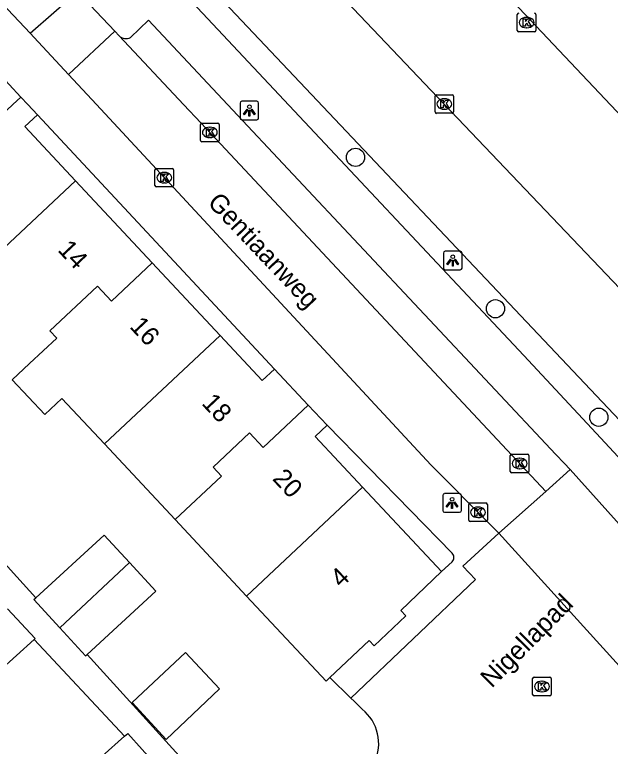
# Model space of a CAD drawing. Extents: x 162347 to 162868, y 381221 to 381813.
# Drawn here: x 162687 to 162719, y 381465.54 to 381504.82 of the extents above; entities that cross this region are included whole.
import ezdxf

# ---------------------------------------------------------------- set-up
doc = ezdxf.new("R2010")
doc.units = 0
for name, color, linetype in [('IMGEO_Boom', 7, 'Continuous'), ('IMGEO_Kolk', 7, 'Continuous'), ('IMGEO_Lichtpunt', 7, 'Continuous'), ('IMGEO_Muur', 7, 'Continuous'), ('IMGEO_Openbare_ruimte_label', 7, 'Continuous'), ('IMGEO_Pand', 7, 'Continuous'), ('IMGEO_Pand_nummerreeks', 7, 'Continuous'), ('IMGEO_Parkeervlak_open', 7, 'Continuous'), ('IMGEO_Rijbaan_lokaal_gesloten', 7, 'Continuous'), ('IMGEO_Rijbaan_lokaal_open', 7, 'Continuous'), ('IMGEO_Voetpad_open', 7, 'Continuous')]:
    doc.layers.add(name, color=color, linetype=linetype)

msp = doc.modelspace()

# ---------------------------------------------------------------- linework, layer by layer
at = {"layer": 'IMGEO_Boom'}
for centre in [(162705.311, 381497.163), (162712.828, 381489.032), (162718.381, 381483.208)]:
    msp.add_circle(centre, 0.489, dxfattribs=at)
at = {"layer": 'IMGEO_Kolk'}
for p, q in [((162714.002, 381503.972), (162714.002, 381504.824)), ((162714.49, 381504.678), (162714.515, 381504.678)), ((162715.003, 381504.824), (162715.003, 381503.972)), ((162714.513, 381504.118), (162714.488, 381504.118)), ((162714.929, 381503.898), (162714.077, 381503.898)), ((162709.581, 381499.599), (162709.581, 381500.451)), ((162709.656, 381500.525), (162710.508, 381500.525)), ((162710.069, 381500.305), (162710.094, 381500.305)), ((162710.582, 381500.451), (162710.582, 381499.599)), ((162710.508, 381499.525), (162709.656, 381499.525)), ((162710.092, 381499.745), (162710.067, 381499.745)), ((162697.06, 381499.001), (162697.912, 381499.001)), ((162696.985, 381498.075), (162696.985, 381498.927)), ((162697.473, 381498.781), (162697.498, 381498.781)), ((162697.986, 381498.927), (162697.986, 381498.075)), ((162697.496, 381498.221), (162697.471, 381498.221)), ((162697.912, 381498.001), (162697.06, 381498.001)), ((162694.537, 381495.645), (162694.537, 381496.497)), ((162694.612, 381496.571), (162695.464, 381496.571)), ((162695.025, 381496.351), (162695.05, 381496.351)), ((162695.538, 381496.497), (162695.538, 381495.645)), ((162695.464, 381495.571), (162694.612, 381495.571)), ((162695.048, 381495.791), (162695.023, 381495.791)), ((162713.626, 381480.298), (162713.626, 381481.15)), ((162713.701, 381481.224), (162714.553, 381481.224)), ((162714.114, 381481.004), (162714.139, 381481.004)), ((162714.627, 381481.15), (162714.627, 381480.298)), ((162714.553, 381480.224), (162713.701, 381480.224)), ((162714.137, 381480.444), (162714.112, 381480.444)), ((162711.466, 381478.603), (162712.318, 381478.603)), ((162711.391, 381477.677), (162711.391, 381478.529)), ((162711.879, 381478.383), (162711.904, 381478.383)), ((162712.392, 381478.529), (162712.392, 381477.677)), ((162711.902, 381477.823), (162711.877, 381477.823)), ((162712.318, 381477.603), (162711.466, 381477.603)), ((162714.825, 381468.323), (162714.825, 381469.175)), ((162714.9, 381469.249), (162715.752, 381469.249)), ((162715.826, 381469.175), (162715.826, 381468.323)), ((162715.313, 381469.029), (162715.338, 381469.029)), ((162715.336, 381468.469), (162715.311, 381468.469)), ((162715.752, 381468.249), (162714.9, 381468.249))]:
    msp.add_line(p, q, dxfattribs=at)
for points in [[(162714.002, 381503.972), (162714.002, 381504.824)], [(162714.323, 381504.598), (162714.446, 381504.598), (162714.446, 381504.447), (162714.576, 381504.598), (162714.74, 381504.598), (162714.594, 381504.447), (162714.747, 381504.198), (162714.595, 381504.198), (162714.51, 381504.362), (162714.446, 381504.295), (162714.446, 381504.198), (162714.323, 381504.198), (162714.323, 381504.598)], [(162715.003, 381504.824), (162715.003, 381503.972)], [(162714.929, 381503.898), (162714.077, 381503.898)], [(162709.581, 381499.599), (162709.581, 381500.451)], [(162709.656, 381500.525), (162710.508, 381500.525)], [(162709.902, 381500.225), (162710.025, 381500.225), (162710.025, 381500.074), (162710.155, 381500.225), (162710.319, 381500.225), (162710.173, 381500.074), (162710.326, 381499.825), (162710.174, 381499.825), (162710.089, 381499.989), (162710.025, 381499.922), (162710.025, 381499.825), (162709.902, 381499.825), (162709.902, 381500.225)], [(162710.582, 381500.451), (162710.582, 381499.599)], [(162710.508, 381499.525), (162709.656, 381499.525)], [(162697.06, 381499.001), (162697.912, 381499.001)], [(162696.985, 381498.075), (162696.985, 381498.927)], [(162697.306, 381498.701), (162697.429, 381498.701), (162697.429, 381498.55), (162697.559, 381498.701), (162697.723, 381498.701), (162697.577, 381498.55), (162697.73, 381498.301), (162697.578, 381498.301), (162697.493, 381498.465), (162697.429, 381498.398), (162697.429, 381498.301), (162697.306, 381498.301), (162697.306, 381498.701)], [(162697.986, 381498.927), (162697.986, 381498.075)], [(162697.912, 381498.001), (162697.06, 381498.001)], [(162694.537, 381495.645), (162694.537, 381496.497)], [(162694.612, 381496.571), (162695.464, 381496.571)], [(162694.858, 381496.271), (162694.981, 381496.271), (162694.981, 381496.12), (162695.111, 381496.271), (162695.275, 381496.271), (162695.129, 381496.12), (162695.282, 381495.871), (162695.13, 381495.871), (162695.045, 381496.035), (162694.981, 381495.968), (162694.981, 381495.871), (162694.858, 381495.871), (162694.858, 381496.271)], [(162695.538, 381496.497), (162695.538, 381495.645)], [(162695.464, 381495.571), (162694.612, 381495.571)], [(162713.626, 381480.298), (162713.626, 381481.15)], [(162713.701, 381481.224), (162714.553, 381481.224)], [(162713.947, 381480.924), (162714.07, 381480.924), (162714.07, 381480.773), (162714.2, 381480.924), (162714.364, 381480.924), (162714.218, 381480.773), (162714.371, 381480.524), (162714.219, 381480.524), (162714.134, 381480.688), (162714.07, 381480.621), (162714.07, 381480.524), (162713.947, 381480.524), (162713.947, 381480.924)], [(162714.627, 381481.15), (162714.627, 381480.298)], [(162714.553, 381480.224), (162713.701, 381480.224)], [(162711.466, 381478.603), (162712.318, 381478.603)], [(162711.391, 381477.677), (162711.391, 381478.529)], [(162711.712, 381478.303), (162711.835, 381478.303), (162711.835, 381478.152), (162711.965, 381478.303), (162712.129, 381478.303), (162711.983, 381478.152), (162712.136, 381477.903), (162711.984, 381477.903), (162711.899, 381478.067), (162711.835, 381478), (162711.835, 381477.903), (162711.712, 381477.903), (162711.712, 381478.303)], [(162712.392, 381478.529), (162712.392, 381477.677)], [(162712.318, 381477.603), (162711.466, 381477.603)], [(162714.825, 381468.323), (162714.825, 381469.175)], [(162714.9, 381469.249), (162715.752, 381469.249)], [(162715.826, 381469.175), (162715.826, 381468.323)], [(162715.146, 381468.949), (162715.269, 381468.949), (162715.269, 381468.798), (162715.399, 381468.949), (162715.563, 381468.949), (162715.417, 381468.798), (162715.57, 381468.549), (162715.418, 381468.549), (162715.333, 381468.713), (162715.269, 381468.646), (162715.269, 381468.549), (162715.146, 381468.549), (162715.146, 381468.949)], [(162715.752, 381468.249), (162714.9, 381468.249)]]:
    msp.add_lwpolyline(points, dxfattribs=at)
for centre, start, end in [((162714.079, 381504.822), 91.552, 178.448), ((162714.079, 381504.822), 91.552, 178.448), ((162714.927, 381504.822), 1.552, 88.448), ((162714.927, 381504.822), 1.552, 88.448), ((162714.079, 381503.974), 181.552, 268.448), ((162714.079, 381503.974), 181.552, 268.448), ((162714.927, 381503.974), 271.552, 358.448), ((162714.927, 381503.974), 271.552, 358.448), ((162709.658, 381500.449), 91.552, 178.448), ((162709.658, 381500.449), 91.552, 178.448), ((162710.506, 381500.449), 1.552, 88.448), ((162710.506, 381500.449), 1.552, 88.448), ((162709.658, 381499.601), 181.552, 268.448), ((162709.658, 381499.601), 181.552, 268.448), ((162710.506, 381499.601), 271.552, 358.448), ((162710.506, 381499.601), 271.552, 358.448), ((162697.062, 381498.925), 91.552, 178.448), ((162697.062, 381498.925), 91.552, 178.448), ((162697.91, 381498.925), 1.552, 88.448), ((162697.91, 381498.925), 1.552, 88.448), ((162697.062, 381498.077), 181.552, 268.448), ((162697.062, 381498.077), 181.552, 268.448), ((162697.91, 381498.077), 271.552, 358.448), ((162697.91, 381498.077), 271.552, 358.448), ((162694.614, 381496.495), 91.552, 178.448), ((162694.614, 381496.495), 91.552, 178.448), ((162695.462, 381496.495), 1.552, 88.448), ((162695.462, 381496.495), 1.552, 88.448), ((162694.614, 381495.647), 181.552, 268.448), ((162694.614, 381495.647), 181.552, 268.448), ((162695.462, 381495.647), 271.552, 358.448), ((162695.462, 381495.647), 271.552, 358.448), ((162713.703, 381481.148), 91.552, 178.448), ((162713.703, 381481.148), 91.552, 178.448), ((162714.551, 381481.148), 1.552, 88.448), ((162714.551, 381481.148), 1.552, 88.448), ((162713.703, 381480.3), 181.552, 268.448), ((162713.703, 381480.3), 181.552, 268.448), ((162714.551, 381480.3), 271.552, 358.448), ((162714.551, 381480.3), 271.552, 358.448), ((162711.468, 381478.527), 91.552, 178.448), ((162711.468, 381478.527), 91.552, 178.448), ((162712.316, 381478.527), 1.552, 88.448), ((162712.316, 381478.527), 1.552, 88.448), ((162711.468, 381477.679), 181.552, 268.448), ((162711.468, 381477.679), 181.552, 268.448), ((162712.316, 381477.679), 271.552, 358.448), ((162712.316, 381477.679), 271.552, 358.448), ((162714.902, 381469.173), 91.552, 178.448), ((162714.902, 381469.173), 91.552, 178.448), ((162715.75, 381469.173), 1.552, 88.448), ((162715.75, 381469.173), 1.552, 88.448), ((162714.902, 381468.325), 181.552, 268.448), ((162714.902, 381468.325), 181.552, 268.448), ((162715.75, 381468.325), 271.552, 358.448), ((162715.75, 381468.325), 271.552, 358.448)]:
    msp.add_arc(centre, 0.0765, start, end, dxfattribs=at)
for centre, major_axis, ratio, start_param, end_param in [((162714.489, 381504.398), (-0.387, 0.002), 0.722429, 4.712389, 7.853982), ((162714.514, 381504.398), (-0.39, 0.002), 0.717154, 1.570796, 4.712389), ((162710.068, 381500.025), (-0.387, 0.002), 0.722429, 4.712389, 7.853982), ((162710.093, 381500.025), (-0.39, 0.002), 0.717154, 1.570796, 4.712389), ((162697.472, 381498.501), (-0.387, 0.002), 0.722429, 4.712389, 7.853982), ((162697.497, 381498.501), (-0.39, 0.002), 0.717154, 1.570796, 4.712389), ((162695.024, 381496.071), (-0.387, 0.002), 0.722429, 4.712389, 7.853982), ((162695.049, 381496.071), (-0.39, 0.002), 0.717154, 1.570796, 4.712389), ((162714.113, 381480.724), (-0.387, 0.002), 0.722429, 4.712389, 7.853982), ((162714.138, 381480.724), (-0.39, 0.002), 0.717154, 1.570796, 4.712389), ((162711.878, 381478.103), (-0.387, 0.002), 0.722429, 4.712389, 7.853982), ((162711.903, 381478.103), (-0.39, 0.002), 0.717154, 1.570796, 4.712389), ((162715.312, 381468.749), (-0.387, 0.002), 0.722429, 4.712389, 7.853982), ((162715.337, 381468.749), (-0.39, 0.002), 0.717154, 1.570796, 4.712389)]:
    msp.add_ellipse(centre, major_axis=major_axis, ratio=ratio, start_param=start_param, end_param=end_param, dxfattribs=at)
at = {"layer": 'IMGEO_Lichtpunt'}
for p, q in [((162700.012, 381500.173), (162699.204, 381500.173)), ((162700.012, 381500.173), (162699.204, 381500.173)), ((162699.11, 381500.078), (162699.11, 381499.271)), ((162699.11, 381500.078), (162699.11, 381499.271)), ((162700.106, 381499.271), (162700.106, 381500.078)), ((162700.106, 381499.271), (162700.106, 381500.078)), ((162699.204, 381499.177), (162700.012, 381499.177)), ((162699.204, 381499.177), (162700.012, 381499.177)), ((162710.036, 381492.024), (162710.036, 381491.217)), ((162710.036, 381492.024), (162710.036, 381491.217)), ((162710.938, 381492.119), (162710.13, 381492.119)), ((162710.938, 381492.119), (162710.13, 381492.119)), ((162711.032, 381491.217), (162711.032, 381492.024)), ((162711.032, 381491.217), (162711.032, 381492.024)), ((162710.13, 381491.123), (162710.938, 381491.123)), ((162710.13, 381491.123), (162710.938, 381491.123)), ((162710, 381479.009), (162710, 381478.202)), ((162710, 381479.009), (162710, 381478.202)), ((162710.902, 381479.104), (162710.094, 381479.104)), ((162710.902, 381479.104), (162710.094, 381479.104)), ((162710.996, 381478.202), (162710.996, 381479.009)), ((162710.996, 381478.202), (162710.996, 381479.009)), ((162710.094, 381478.108), (162710.902, 381478.108)), ((162710.094, 381478.108), (162710.902, 381478.108))]:
    msp.add_line(p, q, dxfattribs=at)
for points in [[(162699.484, 381499.742), (162699.523, 381499.714), (162699.335, 381499.452), (162699.297, 381499.479), (162699.484, 381499.742)], [(162699.586, 381499.694), (162699.633, 381499.694), (162699.633, 381499.372), (162699.586, 381499.372), (162699.586, 381499.694)], [(162699.696, 381499.714), (162699.734, 381499.741), (162699.921, 381499.479), (162699.882, 381499.451), (162699.696, 381499.714)], [(162710.41, 381491.688), (162710.449, 381491.66), (162710.261, 381491.398), (162710.223, 381491.425), (162710.41, 381491.688)], [(162710.512, 381491.64), (162710.559, 381491.64), (162710.559, 381491.318), (162710.512, 381491.318), (162710.512, 381491.64)], [(162710.622, 381491.66), (162710.66, 381491.687), (162710.847, 381491.425), (162710.808, 381491.397), (162710.622, 381491.66)], [(162710.374, 381478.673), (162710.413, 381478.645), (162710.225, 381478.383), (162710.187, 381478.41), (162710.374, 381478.673)], [(162710.476, 381478.625), (162710.523, 381478.625), (162710.523, 381478.303), (162710.476, 381478.303), (162710.476, 381478.625)], [(162710.586, 381478.645), (162710.624, 381478.672), (162710.811, 381478.41), (162710.772, 381478.382), (162710.586, 381478.645)]]:
    msp.add_lwpolyline(points, dxfattribs=at)
for centre in [(162699.609, 381499.876), (162710.535, 381491.822), (162710.499, 381478.807)]:
    msp.add_circle(centre, 0.0994, dxfattribs=at)
for centre, start, end in [((162699.204, 381500.078), 90, 180), ((162699.204, 381500.078), 90, 180), ((162700.012, 381500.078), 0, 90), ((162700.012, 381500.078), 0, 90), ((162699.204, 381499.271), 180, 270), ((162699.204, 381499.271), 180, 270), ((162700.012, 381499.271), 270, 0), ((162700.012, 381499.271), 270, 360), ((162710.13, 381492.024), 90, 180), ((162710.13, 381492.024), 90, 180), ((162710.938, 381492.024), 0, 90), ((162710.938, 381492.024), 0, 90), ((162710.13, 381491.217), 180, 270), ((162710.13, 381491.217), 180, 270), ((162710.938, 381491.217), 270, 0), ((162710.938, 381491.217), 270, 360), ((162710.094, 381479.009), 90, 180), ((162710.094, 381479.009), 90, 180), ((162710.902, 381479.009), 0, 90), ((162710.902, 381479.009), 0, 90), ((162710.094, 381478.202), 180, 270), ((162710.094, 381478.202), 180, 270), ((162710.902, 381478.202), 270, 0), ((162710.902, 381478.202), 270, 360)]:
    msp.add_arc(centre, 0.0946, start, end, dxfattribs=at)
at = {"layer": 'IMGEO_Muur'}
for points in [[(162703.932, 381469.232), (162705.062, 381468.126)], [(162705.062, 381468.126), (162705.231, 381467.961)]]:
    msp.add_lwpolyline(points, dxfattribs=at)
at = {"layer": 'IMGEO_Pand'}
for points in [[(162685.428, 381502.434), (162687.331, 381500.397)], [(162680.182, 381494.241), (162682.618, 381496.526), (162682.168, 381497.006), (162684.134, 381498.851), (162684.86, 381498.078), (162686.909, 381500), (162687.331, 381500.397)], [(162687.331, 381500.397), (162687.702, 381500), (162688.226, 381499.439)], [(162690.269, 381495.907), (162687.555, 381498.812), (162688.226, 381499.439)], [(162690.269, 381495.907), (162684.064, 381490.086)], [(162694.393, 381491.492), (162690.269, 381495.907)], [(162694.393, 381491.492), (162692.205, 381489.448), (162691.458, 381490.245), (162688.899, 381487.855), (162689.271, 381487.459), (162687.801, 381486.086), (162686.874, 381485.22)], [(162698.032, 381487.598), (162694.393, 381491.492)], [(162691.827, 381481.776), (162698.032, 381487.598)], [(162700.964, 381485.794), (162700.298, 381485.172), (162698.032, 381487.598)], [(162700.964, 381485.794), (162702.77, 381483.861)], [(162691.827, 381481.776), (162689.542, 381484.222), (162688.615, 381483.356), (162686.874, 381485.22)], [(162702.77, 381483.861), (162700.35, 381481.591), (162699.624, 381482.364), (162697.658, 381480.519), (162698.108, 381480.039), (162695.626, 381477.71)], [(162702.77, 381483.861), (162703.785, 381482.774)], [(162705.693, 381479.461), (162703.151, 381482.182), (162703.785, 381482.774)], [(162695.626, 381477.71), (162691.827, 381481.776)], [(162705.693, 381479.461), (162699.457, 381473.609)], [(162709.938, 381474.916), (162705.693, 381479.461)], [(162699.457, 381473.609), (162695.626, 381477.71)], [(162688.135, 381473.509), (162691.814, 381476.884), (162693.17, 381475.405)], [(162693.17, 381475.405), (162689.426, 381471.892)], [(162693.17, 381475.405), (162694.585, 381473.863), (162690.89, 381470.473)], [(162709.938, 381474.916), (162707.737, 381472.838), (162708.014, 381472.541), (162706.32, 381470.93), (162706.045, 381471.22), (162703.932, 381469.232)], [(162689.426, 381471.892), (162688.03, 381473.413), (162688.135, 381473.509)], [(162703.932, 381469.232), (162703.726, 381469.038), (162699.457, 381473.609)], [(162688.04, 381471.271), (162688.106, 381471.33), (162686.611, 381472.919)], [(162689.426, 381471.892), (162690.801, 381470.392), (162690.89, 381470.473)], [(162682.774, 381469.473), (162684.241, 381467.846), (162688.04, 381471.271)], [(162696.174, 381470.569), (162697.998, 381468.617), (162695.141, 381465.896), (162693.306, 381467.889), (162696.174, 381470.569)], [(162690.856, 381461.131), (162689.308, 381462.855), (162692.902, 381466.082)], [(162692.902, 381466.082), (162693.073, 381466.235), (162694.62, 381464.512)]]:
    msp.add_lwpolyline(points, dxfattribs=at)
at = {"layer": 'IMGEO_Parkeervlak_open'}
msp.add_lwpolyline([(162723.562, 381478.758), (162664.205, 381541.489)], dxfattribs=at)
at = {"layer": 'IMGEO_Rijbaan_lokaal_gesloten'}
for points in [[(162664.374, 381528.635), (162665.642, 381527.325), (162687.832, 381503.834)], [(162692.384, 381503.933), (162692.611, 381503.69)], [(162692.611, 381503.69), (162696.077, 381500), (162697.02, 381498.996), (162715.531, 381479.221)], [(162713.011, 381476.986), (162712.657, 381477.34), (162709.353, 381480.645), (162691.394, 381500), (162689.902, 381501.609)], [(162715.531, 381479.221), (162713.011, 381476.986)]]:
    msp.add_lwpolyline(points, dxfattribs=at)
at = {"layer": 'IMGEO_Rijbaan_lokaal_open'}
for points in [[(162667.559, 381544.683), (162710.082, 381500.025), (162727.115, 381482.137)], [(162710.386, 381509.124), (162729.211, 381489.182), (162732.348, 381492.129)], [(162687.832, 381503.834), (162690.38, 381506.067)], [(162690.38, 381506.067), (162692.384, 381503.933)], [(162689.902, 381501.609), (162688.05, 381503.604), (162687.832, 381503.834)], [(162689.902, 381501.609), (162692.384, 381503.933)], [(162715.531, 381479.221), (162716.838, 381480.398)], [(162716.838, 381480.398), (162725.57, 381470.679)], [(162705.062, 381468.126), (162711.753, 381474.502), (162711.082, 381475.206), (162713.011, 381476.986)], [(162722.465, 381466.568), (162713.011, 381476.986)], [(162705.669, 381467.533), (162705.231, 381467.961), (162705.062, 381468.126)]]:
    msp.add_lwpolyline(points, dxfattribs=at)
msp.add_arc((162704.186, 381465.683), 2.371, 334.7302, 51.2795, dxfattribs=at)
at = {"layer": 'IMGEO_Voetpad_open'}
for points in [[(162727.352, 381472.54), (162718.237, 381482.347), (162714.352, 381486.527), (162670.77, 381532.927), (162665.411, 381538.603), (162658.834, 381545.613)], [(162693.224, 381503.598), (162694.183, 381504.531), (162698.437, 381500), (162716.08, 381481.206), (162716.52, 381480.737), (162716.838, 381480.398)], [(162688.226, 381499.439), (162700.964, 381485.794)], [(162703.785, 381482.774), (162710.494, 381475.907)], [(162683.29, 381478.831), (162685.58, 381476.325), (162688.135, 381473.509)], [(162710.502, 381475.441), (162709.938, 381474.916)], [(162688.04, 381471.271), (162692.902, 381466.082)], [(162690.89, 381470.473), (162699.002, 381461.533), (162701.237, 381459.381)], [(162705.062, 381468.126), (162703.932, 381469.232)]]:
    msp.add_lwpolyline(points, dxfattribs=at)
for centre, radius, start, end in [((162692.978, 381504.049), 0.513, 224.3125, 298.6168), ((162710.283, 381475.67), 0.317, 313.6972, 48.2699)]:
    msp.add_arc(centre, radius, start, end, dxfattribs=at)

# ---------------------------------------------------------------- texts
at = {"layer": 'IMGEO_Openbare_ruimte_label'}
for s, rotation, p in [('Gentiaanweg', 313.419, (162697.312, 381494.691)), ('Nigellapad', 45.2431, (162712.628, 381468.628))]:
    msp.add_text(s, height=1, rotation=rotation, dxfattribs=at).set_placement(p)
at = {"layer": 'IMGEO_Pand_nummerreeks'}
for s, rotation, p in [('14', 313.2008, (162689.267, 381492.161)), ('16', 313.2008, (162693.133, 381488.044)), ('18', 313.202, (162697.001, 381483.925)), ('20', 313.202, (162700.805, 381479.874)), ('4', 43.4554, (162704.534, 381474.007))]:
    msp.add_text(s, height=1, rotation=rotation, dxfattribs=at).set_placement(p)

doc.saveas('drawing.dxf')
